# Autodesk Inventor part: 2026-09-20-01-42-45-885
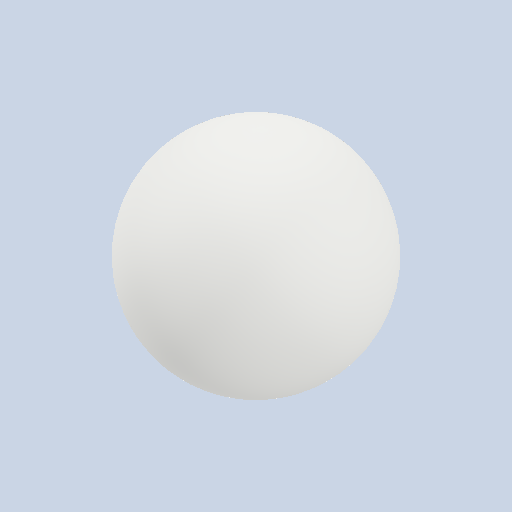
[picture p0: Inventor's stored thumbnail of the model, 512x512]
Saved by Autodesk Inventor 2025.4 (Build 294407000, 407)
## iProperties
Created: 2026-09
Part Number: 2026-09-20-01-42-45-885
Material: Generic
Document SubType Name: Modeling
Designer: AdminForWorker
Density: 1 g/cm^3
Appearance: Default
Title: bolita v1
Author: AdminForWorker
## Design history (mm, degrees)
feature "Body1"
body "Solid1"
